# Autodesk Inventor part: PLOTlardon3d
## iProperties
Author: ajt
Created: 2001-10
Part Number: PLOTlardon3d
Material: Par défaut
Document SubType Name: Proxy Part
Designer: ajt
Control State: 0
Master: False
Checked Out: False
PropertySet Name: Design Tracking Control
Shininess: 21.0
PropertySet Name: _Private Model Information
Length Units: 11269
Angle Units: 11283
Time Units: 11279
Mass Units: 11290
Length Display Precision: 3
Angle Display Precision: 2
Compacted: False
Density: 0.0
Volumn: 0.0
Area: 0.0
PropertySet Name: Model Information
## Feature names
1. LinkedPart1
